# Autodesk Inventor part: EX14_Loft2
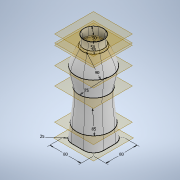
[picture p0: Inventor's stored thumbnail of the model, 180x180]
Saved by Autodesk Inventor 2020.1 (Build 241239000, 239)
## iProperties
Created: 2019-10
Part Number: EX14_Loft2
Material: Generic
Document SubType Name: Modeling
Designer: Synergysoft Dell02
Density: 1 g/cm^3
Appearance: Default
Author: Synergysoft Dell02
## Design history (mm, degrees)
sketch "Sketch1"
  geometry: L1 (15, -40)-(-15, -40); L2 (-40, -15)-(-40, 15); L3 (-15, 40)-(15, 40); L4 (40, 15)-(40, -15); L5 (40, -40)-(-40, 40); L6 (-40, -40)-(40, 40); A1 r 25 centre (15, 15) between (40, 15) and (15, 40); A2 r 25 centre (15, -15) between (15, -40) and (40, -15); A3 r 25 centre (-15, -15) between (-40, -15) and (-15, -40); A4 r 25 centre (-15, 15) between (-15, 40) and (-40, 15); 1 further point
  constraints: 12 end point, 8 point on circle, 8 point on line, 8 tangent, 4 centre point, 3 equal radius, 2 midpoint, 2 parallel, 1 horizontal, 1 perpendicular
  dimensions: "d0" = 80 distance of L5.end L6.end; "d1" = 80 distance of L6.start L5.end; "d2" = 25 radius of A1
workplane "Work Plane1"
sketch "Sketch2"
  geometry: C1 r 42.5 at (0, 0); 1 further point
  constraints: 1 centre point, 1 coincident
  dimensions: "d4" = 85 diameter of C1
workplane "Work Plane2"
sketch "Sketch3"
  geometry: C1 r 37.5 at (0, 0); 1 further point
  constraints: 1 centre point, 1 coincident
  dimensions: "d6" = 75 diameter of C1
workplane "Work Plane3"
sketch "Sketch4"
  geometry: C1 r 45 at (0, 0); 1 further point
  constraints: 1 centre point, 1 coincident
  dimensions: "d8" = 90 diameter of C1
workplane "Work Plane4"
sketch "Sketch5"
  geometry: C1 r 27.5 at (0, 0); 1 further point
  constraints: 1 centre point, 1 coincident
  dimensions: "d10" = 55 diameter of C1
workplane "Work Plane5"
sketch "Sketch6"
  geometry: C1 r 25 at (0, 0); 1 further point
  constraints: 1 centre point, 1 coincident
  dimensions: "d12" = 50 diameter of C1
workplane "Work Plane6"
sketch "Sketch7"
  geometry: C1 r 25 at (0, 0); 1 further point
  constraints: 1 centre point, 1 coincident
  dimensions: "d14" = 50 diameter of C1
loft "Loft1" dims "d15" = 0, "d16" = 90 deg, "d17" = 0, "d18" = 90 deg, "d19" = 0, "d20" = 90 deg, "d21" = 0, "d22" = 90 deg, "d23" = 0, "d24" = 90 deg, "d25" = 0, "d26" = 90 deg, "d27" = 0, "d28" = 90 deg
sketch "Sketch8"
  geometry: L1 (0, 0)-(0, 250)
  constraints: 2 end point, 1 vertical
  dimensions: "d29" = 250 distance of L1.start L1.end
loft "Loft2" sketch "Sketch8" dims "d30" = 0, "d31" = 90 deg, "d32" = 0, "d33" = 90 deg, "d34" = 0, "d35" = 90 deg, "d36" = 0, "d37" = 90 deg, "d38" = 0, "d39" = 90 deg, "d40" = 0, "d41" = 90 deg, "d42" = 0, "d43" = 90 deg, "d44" = 0, "d45" = 90 deg
shell "Shell1" dims "d46" = 1
body "Solid1"
other parameters: "d3" = 35, "d7" = 45, "d9" = 45, "d11" = 5
